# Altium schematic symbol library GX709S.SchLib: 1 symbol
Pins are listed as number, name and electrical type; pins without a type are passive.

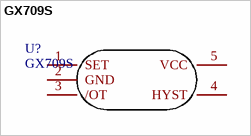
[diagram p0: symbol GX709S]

## GX709S
designator U?
footprint SOT-23-5
pins: 1 SET, 2 GND, 3 /OT, 4 HYST, 5 VCC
